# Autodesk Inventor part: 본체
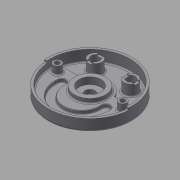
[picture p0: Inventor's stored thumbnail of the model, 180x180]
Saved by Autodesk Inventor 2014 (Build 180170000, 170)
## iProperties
Created: 2015-06
Part Number: 본체
Material: Generic
Document SubType Name: Modeling
Designer: MYHOME
Density: 1 g/cm^3
Appearance: Default
Mass: 382.485 g
Surface Area: 1018.23 cm^2
Volume: 382.485 cm^3
Author: MYHOME
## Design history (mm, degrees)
sketch "스케치4"
  geometry: C1 r 95 at (0, 0); 1 further point
  constraints: 1 centre point, 1 coincident
  dimensions: "d11" = 190 diameter of C1
extrude "돌출4" new body sketch "스케치4" distance "d12" = 32; taper "d13" = 0 deg
sketch "스케치5"
  geometry: C1 r 95 at (0, 0) reference; C2 r 90 at (0, 0)
  constraints: 1 centre point, 1 coincident
  dimensions: "d14" = 180 diameter of C2
extrude "돌출5" cut sketch "스케치5" distance "d15" = 25; taper "d16" = 0 deg
sketch "스케치6"
  geometry: L1 (-90, 0)-(90, 0); L2 (-88.566, 16)-(-38.833, 16); L3 (38.833, 16)-(88.566, 16); A1 r 90 centre (0, 0) between (-90, 0) and (90, 0) reference; A2 r 42 centre (0, 0) between (-38.833, 16) and (38.833, 16)
  constraints: 6 end point, 6 point on circle, 2 parallel, 1 centre point, 1 coincident, 1 horizontal, 1 midpoint
  dimensions: "d17" = 84 diameter of A2; "d19" = 16 distance between parallel lines of L1 L2; "d20" = 16 distance between parallel lines of L1 L3
extrude "돌출6" join sketch "스케치6" distance "d21" = 7; taper "d22" = 0 deg
sketch "스케치8"
  geometry: C1 r 95 at (0, 0) reference; C2 r 11.5 at (0, 0)
  constraints: 1 centre point, 1 coincident
  dimensions: "d37" = 23 diameter of C2
extrude "돌출7" cut sketch "스케치8" stored distance "d38" = 7; taper "d39" = 0 deg
sketch "스케치18"
  geometry: C1 r 15 at (-40, 52); C2 r 15 at (40, 52); A1 r 42 centre (0, 0) between (38.833, 16) and (-38.833, 16) reference
  constraints: 2 centre point
  dimensions: "d57" = 30 diameter of C1; "d58" = 30 diameter of C2; "d59" = 40 horizontal distance of A1.centre C1.centre; "d60" = 80 distance of C2.centre C1.centre; "d61" = 52 vertical distance of A1.centre C1.centre; "d62" = 52 vertical distance of A1.centre C2.centre
extrude "돌출11" join sketch "스케치18" distance "d63" = 25; taper "d64" = 0 deg
sketch "스케치19"
  geometry: C1 r 15 at (0, 0) reference; C2 r 15 at (80, 0) reference; C3 r 10 at (0, 0); C4 r 10 at (80, 0); 1 further point
  constraints: 2 centre point, 2 coincident
  dimensions: "d65" = 20 diameter of C3; "d66" = 20 diameter of C4
extrude "돌출14" cut sketch "스케치19" stored distance "d71" = 25; taper "d72" = 0 deg
sketch "스케치20"
  geometry: L1 (-6, 15)-(6, 15); L2 (6, 15)-(6, -15); L3 (6, -15)-(-6, -15); L4 (-6, -15)-(-6, 15); L5 (65, 6)-(95, 6); L6 (95, 6)-(95, -6); L7 (95, -6)-(65, -6); L8 (65, -6)-(65, 6); C1 r 10 at (0, 0) reference; C2 r 15 at (80, 0) reference; C3 r 10 at (80, 0) reference; 6 further points
  constraints: 16 end point, 4 midpoint, 4 parallel, 3 vertical alignment, 2 horizontal, 2 perpendicular, 1 horizontal alignment, 1 other
  dimensions: "d73" = 12 distance of L2.end L3.end; "d74" = 30 distance of L1.end L2.end; "d75" = 30 distance of L6.end L7.end; "d76" = 12 distance of L7.end L5.start
extrude "돌출15" cut sketch "스케치20" distance "d77" = 3; taper "d78" = 0 deg
sketch "스케치21"
  geometry: L1 (-58.738, -13.549)-(-58.989, -18.549); L2 (-40.761, -14.451)-(-40.999, -19.214); L3 (41, -14)-(41, -19); L4 (59, -14)-(59, -19); C1 r 11.5 at (0, 0) reference; A1 r 50 centre (0, -19) between (-50, -19) and (50, -19); A2 r 59 centre (0, -19) between (-59, -19) and (59, -19); A3 r 41 centre (0, -19) between (-41, -19) and (41, -19); A4 r 9 centre (-50, -19) between (-41, -19) and (-59, -19); A5 r 9 centre (50, -19) between (59, -19) and (41, -19); A6 r 9 centre (-49.749, -14) between (-58.738, -13.549) and (-40.761, -14.451); A7 r 9 centre (50, -14) between (59, -14) and (41, -14)
  constraints: 17 point on circle, 10 tangent, 8 end point, 7 centre point, 2 vertical alignment
  dimensions: "d79" = 41 radius of A3; "d80" = 59 radius of A2; "d81" = 19 distance of C1.centre A1.centre; "d82" = 18 distance of L3.end L4.end; "d83" = 18 distance of A3.start A2.start; "d84" = 18 diameter of A6; "d87" = 5 vertical distance of A1.start A6.centre; "d88" = 18 diameter of A7; "d89" = 5 distance of A1.end A7.centre
extrude "돌출16" cut sketch "스케치21" distance "d90" = 7; taper "d91" = 0 deg
sketch "스케치23"
  geometry: C1 r 11.5 at (0, 0) reference; C2 r 35 at (0, 0); A1 r 42 centre (0, 0) between (38.833, 16) and (-38.833, 16) reference
  constraints: 1 centre point, 1 coincident
  dimensions: "d92" = 70 diameter of C2
extrude "돌출17" join sketch "스케치23" distance "d93" = 10; taper "d94" = 0 deg
sketch "스케치25"
  geometry: L1 (0, 0)-(95, 0); L2 (0, 0)-(94.638, -8.28); L3 (0, 0)-(-94.638, -8.28); A1 r 90 centre (0, 0) between (-89.658, -7.844) and (89.658, -7.844) reference; A2 r 95 centre (0, 0) between (95, 0) and (-94.638, -8.28) reference
  constraints: 6 end point, 5 point on circle, 2 point on line, 1 horizontal
  dimensions: "d99" = 5 deg angle of L1 L3; "d100" = 5 deg angle of L1 L2
extrude "돌출18" cut sketch "스케치25" distance "d101" = 5; taper "d102" = 0 deg
sketch "스케치26"
  geometry: C1 r 35 at (0, 0) reference; C2 r 9 at (-74, 0); C3 r 9 at (74, 0); A1 r 90 centre (0, 0) between (-88.566, 16) and (88.566, 16) reference
  constraints: 2 centre point, 2 horizontal alignment
  dimensions: "d103" = 18 diameter of C2; "d104" = 18 diameter of C3; "d105" = 148 distance of C3.centre C2.centre; "d106" = 74 distance of C1.centre C2.centre
extrude "돌출19" join sketch "스케치26" stored distance "d107" = 5; taper "d108" = 0 deg
sketch "스케치27"
  geometry: C1 r 9 at (0, 0) reference; C2 r 5.5 at (0, 0); C3 r 9 at (-148, 0) reference; C4 r 5.5 at (-148, 0); 1 further point
  constraints: 2 centre point, 2 coincident
  dimensions: "d109" = 11 diameter of C2; "d110" = 11 diameter of C4
extrude "돌출20" cut sketch "스케치27" stored distance "d111" = 5; taper "d112" = 0 deg
sketch "스케치28"
  geometry: C1 r 11.5 at (0, 0) reference; C2 r 95 at (0, 0) reference; A1 r 68 centre (0, 0) between (-20.283, -64.905) and (0, -68)
  constraints: 2 point on circle, 1 centre point, 1 coincident, 1 vertical alignment, 1 other
  dimensions: "d114" = 68 radius of A1
feature "엠보싱1" sketch "스케치28" dims "d115" = 0.5, "d116" = 0
fillet "모깎기1" dims "d117" = 3
fillet "모깎기2" dims "d118" = 3
fillet "모깎기3" dims "d119" = 3
fillet "모깎기4" dims "d120" = 1
sketch "스케치29"
  geometry: C1 r 11.5 at (0, 0) reference; C2 r 35 at (0, 0) reference; C3 r 25 at (0, 0)
  constraints: 1 centre point, 1 coincident
  dimensions: "d121" = 50 diameter of C3
extrude "돌출21" cut sketch "스케치29" distance "d122" = 15; taper "d123" = 0 deg
fillet "모깎기6" dims "d125" = 5
fillet "모깎기7" dims "d127" = 3
fillet "모깎기8" dims "d128" = 3
fillet "모깎기9" dims "d129" = 1
fillet "모깎기10" dims "d130" = 0.3
node "솔리드2"
other parameters: "d8" = 16, "d18" = 16
